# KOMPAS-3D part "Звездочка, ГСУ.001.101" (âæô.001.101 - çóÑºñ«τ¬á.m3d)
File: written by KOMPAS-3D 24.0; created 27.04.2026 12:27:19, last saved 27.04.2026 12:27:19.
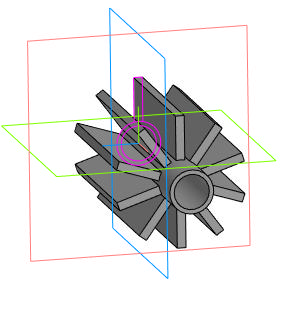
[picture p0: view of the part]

Document properties: Автор: User7; Полное имя файла: C:\Users\User7\Desktop\олимп\ГСУ.001.101 - Звездочка.m3d

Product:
- Part/product: Звездочка  | designation ГСУ.001.101
    Масса: 0.070568

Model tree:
1. Эскиз:1
2. Элемент выдавливания:1
     Расстояние 1 = 48
3. Элемент выдавливания:2
     Расстояние 1 = 38
4. Массив по концентрической сетке:1  (with: Элемент выдавливания:2, Эскиз:1, Грань.Элемент выдавливания:1)  (10 pattern instances)
     Шаг 2 = 360

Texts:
  ГСУ.001.101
